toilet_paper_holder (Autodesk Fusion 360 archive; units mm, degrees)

design "Halter" references "toilet-paper-roll"
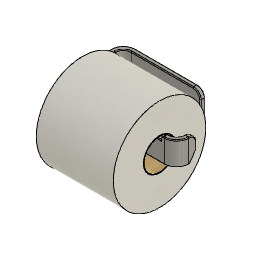
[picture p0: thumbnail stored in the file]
component_insert "Komponente einfügen"
sketch "Skizze1" plane through (0, 0, 0) normal (0, 0, 1) x axis (1, 0, 0)
  line L1 (59, 3) -> (-59, 3)
  line L2 (75, 13) -> (75, 3)
  line L3 (-59, -3) -> (59, -3)
  line L4 (-75, 3) -> (-75, 13)
  line L5 (69, 23) -> (69, 13)
  line L6 (75, 23) -> (69, 23)
  line L7 (75, 3) -> (75, 23)
  line L8 (-69, 62) -> (-69, 13)
  line L9 (-59, 78) -> (-69, 78)
  line L10 (-75, 3) -> (-75, 62)
  line L11 (31, 78) -> (-69, 78)
  line L12 (31, 72) -> (31, 78)
  line L13 (-59, 72) -> (31, 72)
  arc A1 centre (-59, 62) radius 10 clockwise from (-69, 62) to (-59, 72)
  arc A2 centre (-59, 13) radius 10 clockwise from (-59, 3) to (-69, 13)
  arc A3 centre (59, 13) radius 10 clockwise from (69, 13) to (59, 3)
  arc A4 centre (-59, 62) radius 16 clockwise from (-75, 62) to (-59, 78)
  arc A5 centre (-59, 13) radius 16 clockwise from (-59, -3) to (-75, 13)
  arc A6 centre (59, 13) radius 16 clockwise from (75, 13) to (59, -3)
  point P14 (-69, 72)
  point P9 (-69, 3)
  point P6 (69, 3)
  point P11 (-75, 78)
  point P4 (-75, -3)
  point P3 (75, -3)
  point P2 (75, 3)
  point P8 (75, 23)
  point P1 (-75, 3)
  point P10 (-69, 78)
  point P12 (31, 78)
  perpendicular L1 L2
  parallel L1 L3
  parallel L2 L4
  horizontal L1
  vertical L5
  horizontal L6
  vertical L7
  vertical L8
  horizontal L9
  vertical L10
  horizontal L11
  vertical L12
  horizontal L13
  coincident P14 L13
  coincident L8 P14
  tangent L13 A1
  tangent L8 A1
  coincident P9 L8
  coincident L1 P9
  tangent L8 A2
  tangent L1 A2
  equal A1 A2
  coincident P6 L5
  coincident L1 P6
  tangent L5 A3
  tangent L1 A3
  equal A1 A3
  coincident P11 L9
  coincident P11 L10
  tangent L9 A4
  tangent L10 A4
  coincident P4 L3
  coincident P4 L4
  tangent L3 A5
  tangent L4 A5
  equal A4 A5
  coincident P3 L2
  coincident P3 L3
  tangent L2 A6
  tangent L3 A6
  equal A4 A6
  dimension "d1" distance P3 P4 = 150
  dimension "d2" distance P2 P3 = 6
  dimension "d3" distance P2 P8 = 20
  dimension "d4" distance P2 P6 = 6
  dimension "d5" distance P1 P11 = 75
  dimension "d6" distance P1 P9 = 6
  dimension "d7" distance P10 P12 = 100
  dimension "d8" distance P10 P14 = 6
  dimension "d9" radius A1 = 10
  dimension "d10" radius A4 = 16
extrude "Extrusion1" new body sketch "Skizze1" profile of L1 L3 L5 L6 L7 L8 L10 L11 L12 L13 A1 A2 A3 A4 A5 A6 distance 30
sketch "Skizze2" plane through (0, 0, 15) normal (0, 0, 1) x axis (-1, 0, 0)
  line L1 (75, -13) -> (75, -62)
  line L2 (-59, 3) -> (59, 3)
  line L3 (-75, -23) -> (-75, -13)
  line L4 (-69, -23) -> (-75, -23)
  line L5 (-69, -13) -> (-69, -23)
  line L6 (59, -3) -> (-59, -3)
  line L7 (69, -62) -> (69, -13)
  line L8 (-31, -72) -> (59, -72)
  line L9 (-31, -78) -> (-31, -72)
  line L10 (59, -78) -> (-31, -78)
  line L11 (-55, -3) -> (55, -3)
  line L12 (-55, 3) -> (-55, -3)
  line L13 (55, 3) -> (-55, 3)
  line L14 (55, -3) -> (55, 3)
  arc A1 centre (59, -62) radius 16 clockwise from (75, -62) to (59, -78)
  arc A2 centre (59, -13) radius 16 clockwise from (59, 3) to (75, -13)
  arc A3 centre (-59, -13) radius 16 clockwise from (-75, -13) to (-59, 3)
  arc A4 centre (-59, -13) radius 10 clockwise from (-69, -13) to (-59, -3)
  arc A5 centre (59, -13) radius 10 clockwise from (59, -3) to (69, -13)
  arc A6 centre (59, -62) radius 10 clockwise from (69, -62) to (59, -72)
  point P23 (-55, 3)
  point P21 (55, -3)
  horizontal L11
  vertical L12
  horizontal L13
  vertical L14
  coincident L2 P23
  coincident L6 P21
  dimension "d13" distance L12 L14 = 110
  dimension "d14" distance L1 L14 = 20
extrude "Extrusion2" cut sketch "Skizze2" profile of L2 L6 L11 L12 L13 L14 against normal blind 5
fillet "Abrundung1" radius 3
fillet "Abrundung2" radius 10
fillet "Abrundung3" radius 10
chamfer "Fase1" distance 8 distance 12
chamfer "Fase2" distance 0.2
fillet "Abrundung4" radius 10
chamfer "Fase3" distance 1
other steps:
create_component "Komponente erstellen"

design "toilet-paper-roll"
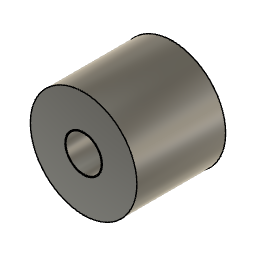
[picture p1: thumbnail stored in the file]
